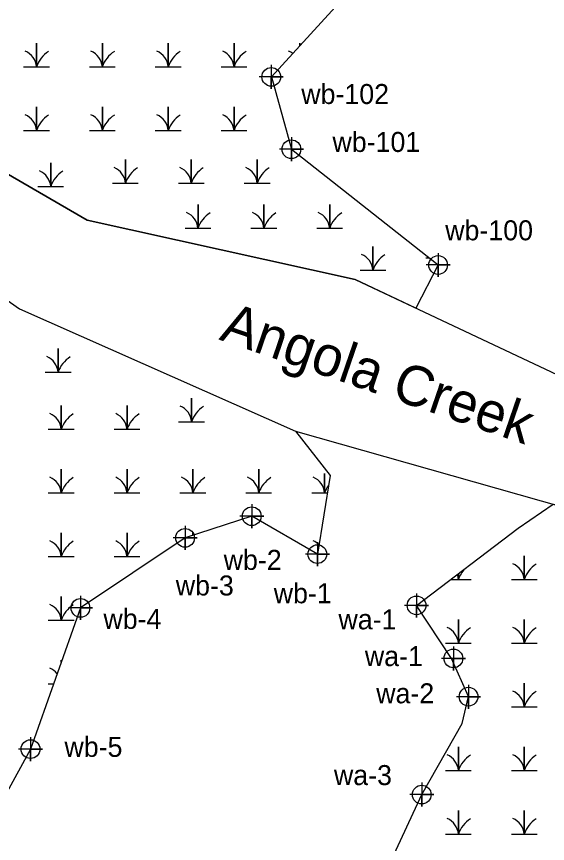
# Model space of a CAD drawing. Extents: x 2379288 to 2381905, y 330670 to 333511.
# Drawn here: x 2380227.2 to 2380359.8, y 332166.7 to 332373.5 of the extents above; entities that cross this region are included whole.
import ezdxf

# ---------------------------------------------------------------- set-up
doc = ezdxf.new("R2010")
doc.units = 0
for name, color, linetype in [('Exist Environmental Wetland Boundary', 7, 'Continuous'), ('Exist Environmental Wetland Boundary Cogo Number', 7, 'Continuous'), ('Exist Environmental Wetland Boundary Cogo Point CELL', 7, 'Continuous'), ('Exist Hydro Jurisdictional Stream or Body of Water Mitigable', 7, 'Continuous'), ('Exist Hydro Jurisdictional Stream or Body of Water Mitigable Text', 7, 'Continuous'), ('Exist Hydro Swamp or Marsh', 7, 'Continuous')]:
    doc.layers.add(name, color=color, linetype=linetype)

msp = doc.modelspace()

# ---------------------------------------------------------------- linework, layer by layer
at = {"layer": 'Exist Environmental Wetland Boundary'}
for points in [[(2380626.94, 332703.59), (2380578.61, 332658.53), (2380538.32, 332619.14), (2380494.95, 332601.64), (2380453.1, 332584.48), (2380406.72, 332572.38), (2380400.16, 332521.26), (2380412.11, 332496.92), (2380413.59, 332462.54), (2380386.06, 332425.71), (2380352.83, 332397.02), (2380315.67, 332385.64), (2380290.84, 332358.39), (2380295.85, 332340.3), (2380332.51, 332311.36), (2380326.97, 332300.58), (2380311.82, 332307.72), (2380244.82, 332322.56), (2380185.2, 332357.15), (2380173.71, 332371.44)], [(2380163.11, 332355.2), (2380184.84, 332330.77), (2380227.89, 332300.41), (2380296.91, 332269.82), (2380305.5, 332258.75), (2380302.34, 332239.07), (2380285.95, 332248.56), (2380269.29, 332243.14), (2380243.15, 332225.62), (2380230.67, 332190.32), (2380205.4, 332144.24), (2380169.42, 332096.94), (2380130.29, 332029.9), (2380102.32, 331972.59)], [(2380190.43, 331937.74), (2380215.91, 331979.8), (2380228.91, 332002.01), (2380260.36, 332058.66), (2380273.37, 332080.17), (2380301.41, 332125.81), (2380310.82, 332140.92), (2380328.42, 332178.94), (2380338.55, 332196.72), (2380340.11, 332203.44), (2380335.84, 332213), (2380327.12, 332226.26), (2380352.5, 332245.53), (2380361.25, 332251.56), (2380391.69, 332242.92), (2380420.68, 332229.92), (2380441.85, 332208.47), (2380413.47, 332149.9), (2380414.24, 332071.02), (2380410.1, 331991.07)]]:
    msp.add_lwpolyline(points, dxfattribs=at)
at = {"layer": 'Exist Environmental Wetland Boundary Cogo Point CELL'}
for points in [[(2380290.83, 332361.39), (2380290.83, 332355.39), (2380290.83, 332358.39), (2380293.83, 332358.39), (2380287.83, 332358.39)], [(2380295.85, 332343.3), (2380295.85, 332337.3), (2380295.85, 332340.3), (2380298.85, 332340.3), (2380292.85, 332340.3)], [(2380332.51, 332314.36), (2380332.51, 332308.36), (2380332.51, 332311.36), (2380335.51, 332311.36), (2380329.51, 332311.36)], [(2380285.95, 332251.56), (2380285.95, 332245.56), (2380285.95, 332248.56), (2380288.95, 332248.56), (2380282.95, 332248.56)], [(2380269.29, 332246.14), (2380269.29, 332240.14), (2380269.29, 332243.14), (2380272.29, 332243.14), (2380266.29, 332243.14)], [(2380302.34, 332242.07), (2380302.34, 332236.07), (2380302.34, 332239.07), (2380305.34, 332239.07), (2380299.34, 332239.07)], [(2380243.15, 332228.62), (2380243.15, 332222.62), (2380243.15, 332225.62), (2380246.15, 332225.62), (2380240.15, 332225.62)], [(2380327.12, 332229.26), (2380327.12, 332223.26), (2380327.12, 332226.26), (2380330.12, 332226.26), (2380324.12, 332226.26)], [(2380336.32, 332216), (2380336.32, 332210), (2380336.32, 332213), (2380339.32, 332213), (2380333.32, 332213)], [(2380340.11, 332206.43), (2380340.11, 332200.43), (2380340.11, 332203.43), (2380343.11, 332203.43), (2380337.11, 332203.43)], [(2380230.67, 332193.32), (2380230.67, 332187.32), (2380230.67, 332190.32), (2380233.67, 332190.32), (2380227.67, 332190.32)], [(2380328.42, 332181.94), (2380328.42, 332175.94), (2380328.42, 332178.94), (2380331.42, 332178.94), (2380325.42, 332178.94)]]:
    msp.add_lwpolyline(points, dxfattribs=at)
for centre in [(2380290.83, 332358.39), (2380295.85, 332340.3), (2380332.51, 332311.36), (2380285.95, 332248.56), (2380269.29, 332243.14), (2380302.34, 332239.07), (2380243.15, 332225.62), (2380327.12, 332226.26), (2380336.32, 332213), (2380340.11, 332203.43), (2380230.67, 332190.32), (2380328.42, 332178.94)]:
    msp.add_circle(centre, 2.34, dxfattribs=at)
at = {"layer": 'Exist Hydro Jurisdictional Stream or Body of Water Mitigable'}
for points in [[(2380185.2, 332357.15), (2380244.82, 332322.56), (2380311.82, 332307.72), (2380399.67, 332266.29), (2380440.55, 332246.83), (2380463.17, 332209.13), (2380430.27, 332144.34), (2380445.79, 332068.31), (2380442.38, 332045.91)], [(2380184.84, 332330.77), (2380227.89, 332300.41), (2380296.91, 332269.82), (2380391.69, 332242.92), (2380420.68, 332229.92), (2380441.85, 332208.47), (2380413.47, 332149.9), (2380414.24, 332071.02), (2380410.1, 331991.07)]]:
    msp.add_lwpolyline(points, dxfattribs=at)
at = {"layer": 'Exist Hydro Swamp or Marsh'}
for p, q in [((2380329.48, 332313.16), (2380330.22, 332313.16)), ((2380235.12, 332206.61), (2380236.43, 332206.61))]:
    msp.add_line(p, q, dxfattribs=at)
for points in [[(2380228.94, 332360.92), (2380232.17, 332360.92), (2380232.17, 332366.83), (2380232.17, 332360.92), (2380235.39, 332360.92)], [(2380245.39, 332360.92), (2380248.62, 332360.92), (2380248.62, 332366.83), (2380248.62, 332360.92), (2380251.84, 332360.92)], [(2380261.84, 332360.92), (2380265.07, 332360.92), (2380265.07, 332366.83), (2380265.07, 332360.92), (2380268.29, 332360.92)], [(2380278.29, 332360.92), (2380281.52, 332360.92), (2380281.52, 332366.83), (2380281.52, 332360.92), (2380284.74, 332360.92)], [(2380297.97, 332366.21), (2380297.97, 332366.83), (2380297.97, 332366.21)], [(2380228.94, 332345), (2380232.17, 332345), (2380232.17, 332350.92), (2380232.17, 332345), (2380235.39, 332345)], [(2380245.39, 332345), (2380248.62, 332345), (2380248.62, 332350.92), (2380248.62, 332345), (2380251.84, 332345)], [(2380261.84, 332345), (2380265.07, 332345), (2380265.07, 332350.92), (2380265.07, 332345), (2380268.29, 332345)], [(2380278.29, 332345), (2380281.52, 332345), (2380281.52, 332350.92), (2380281.52, 332345), (2380284.74, 332345)], [(2380251.16, 332331.8), (2380254.39, 332331.8), (2380254.39, 332337.72), (2380254.39, 332331.8), (2380257.61, 332331.8)], [(2380267.61, 332331.8), (2380270.84, 332331.8), (2380270.84, 332337.72), (2380270.84, 332331.8), (2380274.06, 332331.8)], [(2380284.06, 332331.8), (2380287.29, 332331.8), (2380287.29, 332337.72), (2380287.29, 332331.8), (2380290.51, 332331.8)], [(2380232.5, 332330.98), (2380235.73, 332330.98), (2380235.73, 332336.9), (2380235.73, 332330.98), (2380238.95, 332330.98)], [(2380269.29, 332320.54), (2380272.52, 332320.54), (2380272.52, 332326.45), (2380272.52, 332320.54), (2380275.74, 332320.54)], [(2380285.74, 332320.54), (2380288.97, 332320.54), (2380288.97, 332326.45), (2380288.97, 332320.54), (2380292.2, 332320.54)], [(2380302.2, 332320.54), (2380305.42, 332320.54), (2380305.42, 332326.45), (2380305.42, 332320.54), (2380308.65, 332320.54)], [(2380313, 332310.09), (2380316.22, 332310.09), (2380316.22, 332316.01), (2380316.22, 332310.09), (2380319.45, 332310.09)], [(2380234.34, 332284.53), (2380237.56, 332284.53), (2380237.56, 332290.45), (2380237.56, 332284.53), (2380240.79, 332284.53)], [(2380267.67, 332272.16), (2380270.89, 332272.16), (2380270.89, 332278.08), (2380270.89, 332272.16), (2380274.12, 332272.16)], [(2380235.12, 332270.28), (2380238.34, 332270.28), (2380238.34, 332276.2), (2380238.34, 332270.28), (2380241.57, 332270.28)], [(2380251.57, 332270.28), (2380254.79, 332270.28), (2380254.79, 332276.2), (2380254.79, 332270.28), (2380258.02, 332270.28)], [(2380235.12, 332254.37), (2380238.34, 332254.37), (2380238.34, 332260.28), (2380238.34, 332254.37), (2380241.57, 332254.37)], [(2380251.57, 332254.37), (2380254.79, 332254.37), (2380254.79, 332260.28), (2380254.79, 332254.37), (2380258.02, 332254.37)], [(2380268.02, 332254.37), (2380271.24, 332254.37), (2380271.24, 332260.28), (2380271.24, 332254.37), (2380274.47, 332254.37)], [(2380284.47, 332254.37), (2380287.7, 332254.37), (2380287.7, 332260.28), (2380287.7, 332254.37), (2380290.92, 332254.37)], [(2380300.92, 332254.37), (2380304.15, 332254.37), (2380304.15, 332259.22)], [(2380304.15, 332259.22), (2380304.15, 332254.37), (2380304.79, 332254.37)], [(2380235.12, 332238.45), (2380238.34, 332238.45), (2380238.34, 332244.37), (2380238.34, 332238.45), (2380241.57, 332238.45)], [(2380251.57, 332238.45), (2380254.79, 332238.45), (2380254.79, 332244.37), (2380254.79, 332238.45), (2380258.02, 332238.45)], [(2380271.24, 332243.78), (2380271.24, 332244.37), (2380271.24, 332243.78)], [(2380350.8, 332232.72), (2380354.03, 332232.72), (2380354.03, 332238.64), (2380354.03, 332232.72), (2380357.25, 332232.72)], [(2380335.63, 332232.72), (2380337.57, 332232.72), (2380337.57, 332234.2)], [(2380337.57, 332234.2), (2380337.57, 332232.72), (2380340.8, 332232.72)], [(2380235.12, 332222.53), (2380238.34, 332222.53), (2380238.34, 332228.45), (2380238.34, 332222.53), (2380241.57, 332222.53)], [(2380334.35, 332216.8), (2380337.57, 332216.8), (2380337.57, 332222.72), (2380337.57, 332216.8), (2380340.8, 332216.8)], [(2380350.8, 332216.8), (2380354.03, 332216.8), (2380354.03, 332222.72), (2380354.03, 332216.8), (2380357.25, 332216.8)], [(2380238.34, 332212.03), (2380238.34, 332212.53), (2380238.34, 332212.03)], [(2380350.8, 332200.88), (2380354.03, 332200.88), (2380354.03, 332206.8), (2380354.03, 332200.88), (2380357.25, 332200.88)], [(2380334.35, 332184.96), (2380337.57, 332184.96), (2380337.57, 332190.88), (2380337.57, 332184.96), (2380340.8, 332184.96)], [(2380350.8, 332184.96), (2380354.03, 332184.96), (2380354.03, 332190.88), (2380354.03, 332184.96), (2380357.25, 332184.96)], [(2380334.35, 332169.05), (2380337.57, 332169.05), (2380337.57, 332174.96), (2380337.57, 332169.05), (2380340.8, 332169.05)], [(2380350.8, 332169.05), (2380354.03, 332169.05), (2380354.03, 332174.96), (2380354.03, 332169.05), (2380357.25, 332169.05)]]:
    msp.add_lwpolyline(points, dxfattribs=at)
for centre, radius, start, end in [((2380227.57, 332360.58), 4.61, 4.1403, 67.535), ((2380239.01, 332358.64), 7.21, 122.1274, 161.6222), ((2380244.02, 332360.58), 4.61, 4.1403, 67.535), ((2380255.46, 332358.64), 7.21, 122.1274, 161.6222), ((2380260.47, 332360.58), 4.61, 4.1403, 67.535), ((2380271.91, 332358.64), 7.21, 122.1274, 161.6222), ((2380276.92, 332360.58), 4.61, 4.1403, 67.535), ((2380288.36, 332358.64), 7.21, 122.1274, 161.6222), ((2380293.37, 332360.58), 4.61, 52.5524, 67.535), ((2380227.57, 332344.66), 4.61, 4.1403, 67.535), ((2380239.01, 332342.72), 7.21, 122.1274, 161.6222), ((2380244.02, 332344.66), 4.61, 4.1403, 67.535), ((2380255.46, 332342.72), 7.21, 122.1274, 161.6222), ((2380260.47, 332344.66), 4.61, 4.1403, 67.535), ((2380271.91, 332342.72), 7.21, 122.1274, 161.6222), ((2380276.92, 332344.66), 4.61, 4.1403, 67.535), ((2380288.36, 332342.72), 7.21, 122.1274, 161.6222), ((2380249.79, 332331.47), 4.61, 4.1403, 67.535), ((2380261.23, 332329.53), 7.21, 122.1274, 161.6222), ((2380266.24, 332331.47), 4.61, 4.1403, 67.535), ((2380277.68, 332329.53), 7.21, 122.1274, 161.6222), ((2380282.69, 332331.47), 4.61, 4.1403, 67.535), ((2380294.13, 332329.53), 7.21, 122.1274, 161.6222), ((2380231.13, 332330.64), 4.61, 4.1403, 67.535), ((2380242.57, 332328.71), 7.21, 122.1274, 161.6222), ((2380267.92, 332320.2), 4.61, 4.1403, 67.535), ((2380279.36, 332318.26), 7.21, 122.1274, 161.6222), ((2380284.37, 332320.2), 4.61, 4.1403, 67.535), ((2380295.81, 332318.26), 7.21, 122.1274, 161.6222), ((2380300.82, 332320.2), 4.61, 4.1403, 67.535), ((2380312.26, 332318.26), 7.21, 122.1274, 161.6222), ((2380311.62, 332309.76), 4.61, 4.1403, 67.535), ((2380323.06, 332307.82), 7.21, 122.1274, 161.6222), ((2380232.96, 332284.2), 4.61, 4.1403, 67.535), ((2380244.4, 332282.26), 7.21, 122.1274, 161.6222), ((2380266.29, 332271.83), 4.61, 4.1403, 67.535), ((2380277.73, 332269.89), 7.21, 122.1274, 161.6222), ((2380233.74, 332269.95), 4.61, 4.1403, 67.535), ((2380245.18, 332268.01), 7.21, 122.1274, 161.6222), ((2380250.19, 332269.95), 4.61, 4.1403, 67.535), ((2380261.63, 332268.01), 7.21, 122.1274, 161.6222), ((2380233.74, 332254.03), 4.61, 4.1403, 67.535), ((2380245.18, 332252.09), 7.21, 122.1274, 161.6222), ((2380250.19, 332254.03), 4.61, 4.1403, 67.535), ((2380261.63, 332252.09), 7.21, 122.1274, 161.6222), ((2380266.65, 332254.03), 4.61, 4.1403, 67.535), ((2380278.09, 332252.09), 7.21, 122.1274, 161.6222), ((2380283.1, 332254.03), 4.61, 4.1403, 67.535), ((2380294.54, 332252.09), 7.21, 122.1274, 161.6222), ((2380299.55, 332254.03), 4.61, 4.1403, 67.535), ((2380310.99, 332252.09), 7.21, 144.8366, 161.6222), ((2380233.74, 332238.12), 4.61, 4.1403, 67.535), ((2380245.18, 332236.18), 7.21, 122.1274, 161.6222), ((2380250.19, 332238.12), 4.61, 4.1403, 67.535), ((2380261.63, 332236.18), 7.21, 122.1274, 161.6222), ((2380299.55, 332238.12), 4.61, 46.4337, 67.535), ((2380349.43, 332232.38), 4.61, 4.1403, 67.535), ((2380360.87, 332230.44), 7.21, 122.1274, 161.6222), ((2380332.98, 332232.38), 4.61, 4.1403, 20.3241), ((2380344.42, 332230.44), 7.21, 136.0217, 161.6222), ((2380233.74, 332222.2), 4.61, 4.1403, 67.535), ((2380245.18, 332220.26), 7.21, 122.1274, 161.6222), ((2380332.98, 332216.47), 4.61, 4.1403, 67.535), ((2380344.42, 332214.53), 7.21, 122.1274, 161.6222), ((2380349.43, 332216.47), 4.61, 4.1403, 67.535), ((2380360.87, 332214.53), 7.21, 122.1274, 161.6222), ((2380233.74, 332206.28), 4.61, 38.8593, 67.535), ((2380349.43, 332200.55), 4.61, 4.1403, 67.535), ((2380360.87, 332198.61), 7.21, 122.1274, 161.6222), ((2380332.98, 332184.63), 4.61, 4.1403, 67.535), ((2380344.42, 332182.69), 7.21, 122.1274, 161.6222), ((2380349.43, 332184.63), 4.61, 4.1403, 67.535), ((2380360.87, 332182.69), 7.21, 122.1274, 161.6222), ((2380332.98, 332168.71), 4.61, 4.1403, 67.535), ((2380344.42, 332166.77), 7.21, 122.1274, 161.6222), ((2380349.43, 332168.71), 4.61, 4.1403, 67.535), ((2380360.87, 332166.77), 7.21, 122.1274, 161.6222)]:
    msp.add_arc(centre, radius, start, end, dxfattribs=at)

# ---------------------------------------------------------------- texts
at = {"layer": 'Exist Environmental Wetland Boundary Cogo Number'}
for s, p in [('wb-102', (2380298.32, 332351.61)), ('wb-101', (2380306.11, 332339.62)), ('wb-100', (2380334.28, 332317.53)), ('wb-2', (2380278.93, 332235.13)), ('wb-3', (2380266.97, 332228.73)), ('wb-1', (2380291.44, 332226.78)), ('wb-4', (2380248.89, 332220.38)), ('wa-1', (2380307.61, 332220.26)), ('wa-1', (2380314.21, 332211.07)), ('wa-2', (2380317.04, 332201.77)), ('wb-5', (2380239.15, 332188.38)), ('wa-3', (2380306.48, 332181.32))]:
    msp.add_text(s, height=5, dxfattribs=at).set_placement(p)
at = {"layer": 'Exist Hydro Jurisdictional Stream or Body of Water Mitigable Text'}
msp.add_text('Angola Creek', height=10, rotation=341.0497, dxfattribs=at).set_placement((2380277.57, 332292.76))

doc.saveas('drawing.dxf')
